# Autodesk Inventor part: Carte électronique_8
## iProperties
Created: 2010-07
Part Number: Carte électronique_8
Document SubType Name: Modeling
Designer: eric
Density: 1 g/cm^3
Author: eric
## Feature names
1. Base1
